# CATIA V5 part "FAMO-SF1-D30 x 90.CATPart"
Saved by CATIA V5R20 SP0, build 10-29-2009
Part number: FAMO-SF1-D30 x 90
Definition: NONE
Nomenclature: FAMO-SF1-D30 x 90
Source: Unknown
Description: FAMO-SF1-D30 x 90
Bounding box of the stored display mesh (mm): x -53 to 37, y -26.5 to 26.5, z -26.5 to 26.5
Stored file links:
  C:\Users\Utente\Desktop\IO LAVORO\3D X SITO CF\X SITO\FAMO\FAMO-SF1-D30 x 90.CATPart
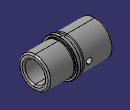
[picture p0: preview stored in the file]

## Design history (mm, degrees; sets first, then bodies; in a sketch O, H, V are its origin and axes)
Body1 "FAMO-SF1-D30 x 90" (main body)
  Solid1: solid without history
